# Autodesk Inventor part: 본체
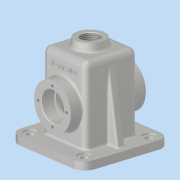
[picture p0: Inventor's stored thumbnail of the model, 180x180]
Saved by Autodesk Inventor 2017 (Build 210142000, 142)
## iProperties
Part Number: 본체
Material: 알루미늄 6061
Document SubType Name: Modeling
Designer: MRC
Density: 2.7 g/cm^3
Appearance: 알루미늄 - 평지
Mass: 748.788 g
Surface Area: 864.325 cm^2
Volume: 277.329 cm^3
Author: MRC
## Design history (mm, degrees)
sketch "스케치1"
  geometry: L1 (-34, 53)-(34, 53); L2 (34, 53)-(34, -52); L3 (34, -52)-(-34, -52); L4 (-34, -52)-(-34, 53); 2 further points
  constraints: 8 end point, 2 parallel, 1 horizontal, 1 midpoint, 1 perpendicular, 1 vertical alignment
  dimensions: "d0" = 68 distance of L2.end L3.end; "d1" = 105 distance of L1.end L2.end; "d2" = 52 distance from line of L3 point (0, 0)
extrude "돌출1" new body sketch "스케치1" stored distance "d3" = 68; taper "d4" = 0 deg
fillet "모깎기1" dims "d5" = 8
fillet "모깎기2" dims "d6" = 8
feature "쉘1" dims "d7" = 5
node "작업 평면1"
sketch "스케치2"
  geometry: C1 r 28.5 at (0, 0); 1 further point
  constraints: 1 centre point, 1 coincident
  dimensions: "d9" = 57 diameter of C1
extrude "돌출2" join sketch "스케치2" stored distance "d10" = 68; taper "d11" = 0 deg
sketch "스케치3"
  geometry: C1 r 28.5 at (0, 0) reference; C2 r 17.5 at (0, 0)
  constraints: 1 centre point, 1 coincident
  dimensions: "d12" = 35 diameter of C2
extrude "돌출3" cut sketch "스케치3" distance "d13" = 17; taper "d14" = 0 deg
sketch "스케치4"
  geometry: C1 r 17.5 at (0, 0) reference; C2 r 15 at (0, 0)
  constraints: 1 centre point, 1 coincident
  dimensions: "d15" = 30 diameter of C2
extrude "돌출4" cut sketch "스케치4" stored distance "d16" = 17; taper "d17" = 0 deg
sketch "스케치5"
  geometry: C1 r 17.5 at (0, 0) reference; 1 further point
  constraints: 1 vertical alignment
  dimensions: "d74" = 22 distance of C1.centre point (0, 22)
hole "구멍1" sketch "스케치5" at (0, 22) diameter "d18" = 3.242; stored, may be unused: countersink angle "d22" = 90 deg, drill point angle "d24" = 118 deg; dims "d19" = 8, "d20" = 4, "d21" = 2, "d23" = 10
sketch "스케치6"
  geometry: C1 r 20 at (26, 26); 1 further point
  constraints: 1 centre point, 1 coincident
  dimensions: "d28" = 40 diameter of C1
extrude "돌출5" join sketch "스케치6" distance "d29" = 10; taper "d30" = 0 deg
sketch "스케치7"
  geometry: C1 r 20 at (0, 0) reference
hole "구멍2" sketch "스케치7" at (0, 0) diameter "d31" = 22.835; stored, may be unused: countersink angle "d35" = 90 deg, drill point angle "d37" = 118 deg; dims "d32" = 100, "d33" = 4, "d34" = 2, "d36" = 100
feature "면 기울기1" dims angle "d38" = 8 deg
sketch "스케치8"
  geometry: L1 (-8, 60)-(-8, 8) reference; L2 (52, 0)-(0, 0) reference; L3 (60, 60)-(60, 8) reference; L4 (0, 68)-(52, 68) reference; L5 (83, -23)-(-31, -23); L6 (-31, -23)-(-31, 91); L7 (-31, 91)-(83, 91); L8 (83, 91)-(83, -23); L9 (83, -23)-(-31, 91); L10 (-31, -23)-(83, 91); A1 r 8 centre (0, 60) between (0, 68) and (-8, 60) reference; A2 r 8 centre (0, 8) between (-8, 8) and (0, 0) reference; A3 r 8 centre (52, 8) between (52, 0) and (60, 8) reference; A4 r 8 centre (52, 60) between (60, 60) and (52, 68) reference; 1 further point
  constraints: 12 end point, 2 midpoint, 2 parallel, 1 horizontal, 1 perpendicular
  dimensions: "d39" = 114 distance of L6.end L7.end; "d40" = 114 distance of L5.end L6.end
extrude "돌출6" join sketch "스케치8" distance "d41" = 10; taper "d42" = 0 deg
fillet "모깎기3" dims "d43" = 15
sketch "스케치10"
  geometry: L1 (57, -42)-(57, -52) reference; L2 (42, -42)-(57, -42) reference; L3 (42.569, -5.525)-(49, -42); 1 further point
  constraints: 2 end point, 1 point on line
  dimensions: "d46" = 8 distance from line of L1 L3.end; "d47" = 10 deg angle of L1 L3
feature "리브1" sketch "스케치10" dims "d48" = 1, "d49" = 10, "d50" = 0, "d51" = 0, "d52" = 1, "d53" = 1
fillet "모깎기4" dims "d54" = 3
fillet "모깎기5" dims "d55" = 3
fillet "모깎기6" dims "d56" = 3
fillet "모깎기7" dims "d57" = 3
fillet "모깎기8" dims "d58" = 3
sketch "스케치11"
  geometry: A1 r 15 centre (68, 8) between (83, 8) and (68, 23) reference; A2 r 15 centre (-16, 8) between (-16, 23) and (-31, 8) reference; A3 r 15 centre (-16, -76) between (-31, -76) and (-16, -91) reference; A4 r 15 centre (68, -76) between (68, -91) and (83, -76) reference; 1 further point
hole "구멍3" sketch "스케치11" at (68, -76), (-16, -76), (-16, 8), (68, 8) diameter "d59" = 10; stored, may be unused: countersink angle "d63" = 90 deg, drill point angle "d65" = 118 deg; dims "d60" = 100, "d61" = 18, "d62" = 2, "d64" = 100
fillet "모깎기9" dims "d66" = 0.3
chamfer "모따기1" distance "d67" = 1; stored, may be unused: second distance "d68" = 2, angle "d69" = 45 deg
sketch "스케치12"
  geometry: L1 (-34, 45)-(-34, -39) reference; L2 (18.595, 63)-(-18.595, 63) reference; 1 further point
  constraints: 1 other
  dimensions: "d70" = 34 distance from line of L1 point (0, 38); "d71" = 25 distance from line of point (0, 38) L2
feature "엠보싱1" sketch "스케치12" dims "d0" = 68, "d1" = 105, "d2" = 52, "d72" = 1, "d73" = 0
chamfer "모따기2" distance "d75" = 1; stored, may be unused: second distance "d76" = 2, angle "d77" = 45 deg
node "솔리드1"
pattern_circular "원형 패턴1" dims angle "d26" = 360 deg
mirror "미러1"
mirror "미러2"
other parameters: "d8" = 15
